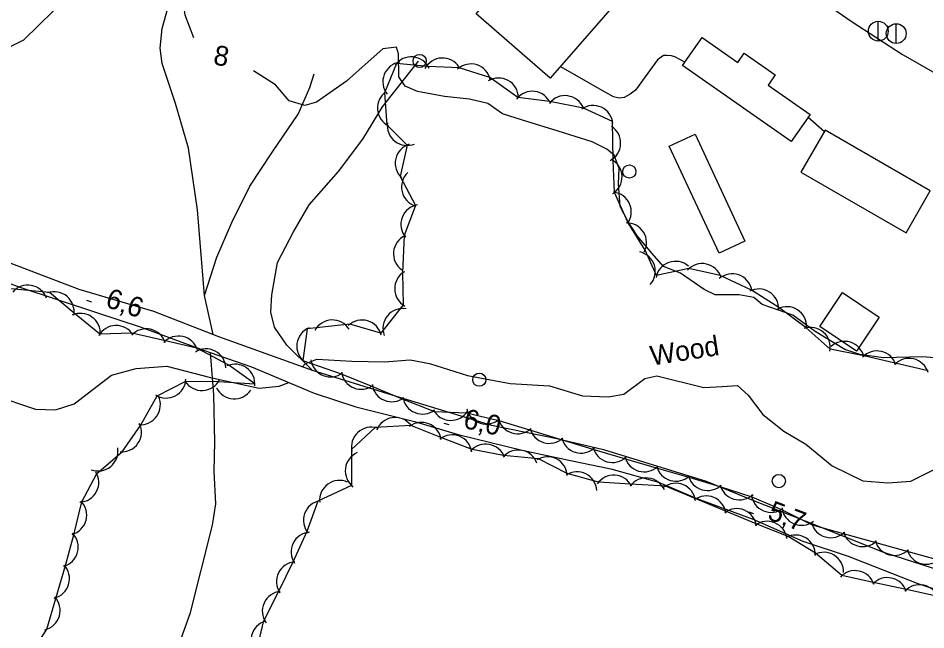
# Model space of a CAD drawing. Extents: x 646142 to 649934, y 5874075 to 5876351.
# Drawn here: x 646580.4 to 646717.7, y 5874651.3 to 5874743.9 of the extents above; entities that cross this region are included whole.
import ezdxf

# ---------------------------------------------------------------- set-up
doc = ezdxf.new("R2010")
doc.units = 0
for name, color, linetype in [('Niveau 19', 7, 'Continuous'), ('Niveau 2', 7, 'Continuous'), ('Niveau 21', 7, 'Continuous'), ('Niveau 22', 7, 'Continuous'), ('Niveau 3', 7, 'Continuous'), ('Niveau 31', 7, 'Continuous'), ('Niveau 36', 7, 'Continuous'), ('Niveau 44', 7, 'Continuous')]:
    doc.layers.add(name, color=color, linetype=linetype)

msp = doc.modelspace()

# ---------------------------------------------------------------- linework, layer by layer
at = {"layer": 'Niveau 19'}
for points in [[(646681.21, 5874737.17), (646679.7, 5874738.02), (646679.19, 5874738.17), (646678.52, 5874738.2), (646677.98, 5874738.18), (646677.09, 5874737.56), (646673.73, 5874732.96), (646672.93, 5874732.32), (646672.04, 5874731.85), (646671.29, 5874731.73), (646670.45, 5874731.95), (646669.14, 5874732.66), (646662.38, 5874736.51)], [(646699.88, 5874728.86), (646702.32, 5874726.69)]]:
    msp.add_lwpolyline(points, dxfattribs=at)
at = {"layer": 'Niveau 2'}
for points in [[(646606.93, 5874740.89), (646605.65, 5874744.31), (646605.35, 5874746.52), (646603.65, 5874747.15), (646600.75, 5874748.92), (646599.25, 5874748.62), (646596.57, 5874747.77), (646593.24, 5874747.5), (646589.33, 5874746.55), (646585.76, 5874745.03), (646581.21, 5874740.5), (646577.43, 5874738.67)], [(646721.94, 5874692.2), (646717.17, 5874692.58), (646711.27, 5874692.46), (646707.66, 5874692.94), (646705.43, 5874693.7), (646700.93, 5874696.45), (646697.57, 5874698.88), (646692.93, 5874700.51), (646691.67, 5874701.58), (646689.41, 5874701.99), (646685.78, 5874701.99), (646684.14, 5874702.8), (646680.54, 5874705.27), (646678, 5874706.25), (646676.25, 5874708.22), (646674.04, 5874710.86), (646672.63, 5874713.04), (646671.45, 5874715.35), (646671.16, 5874718.8), (646671.27, 5874721.09), (646670.52, 5874723.09), (646669.44, 5874724), (646667.19, 5874725.11), (646662.07, 5874726.76), (646656.66, 5874728.39), (646653.65, 5874729.38), (646651.42, 5874730.91), (646648.67, 5874731.57), (646644.88, 5874731.98), (646640.78, 5874732.77), (646638.89, 5874733.56), (646637.96, 5874734.95), (646637.9, 5874738.47), (646637.59, 5874739.44), (646635.56, 5874739.22), (646633.32, 5874737.23), (646630.04, 5874734.32), (646625.5, 5874731.14), (646623.72, 5874730.65), (646621.38, 5874731.34), (646619.3, 5874733.76), (646615.98, 5874735.88)], [(646483.74, 5874706.15), (646502.21, 5874704.49), (646520.99, 5874699.39), (646534.02, 5874696.13), (646543.68, 5874692.42), (646552.55, 5874691.13), (646563.43, 5874690.35), (646576.66, 5874686.81), (646583, 5874684.67)], [(646623.41, 5874691.08), (646623.79, 5874691.51), (646625.55, 5874692.24), (646630.86, 5874691.96), (646635.8, 5874691.82), (646639.65, 5874692.13), (646642.57, 5874691.6), (646648.35, 5874689.77), (646654.79, 5874688.57), (646660.74, 5874688.23), (646665.74, 5874686.68), (646669.63, 5874686.52), (646672, 5874686.95), (646675.14, 5874689.32), (646676.99, 5874689.7), (646684.11, 5874687.97), (646686.86, 5874688.08), (646689.19, 5874688.26), (646690.77, 5874686.8), (646693.01, 5874683.86), (646696.21, 5874681.36), (646699.54, 5874679.39), (646703.5, 5874676.12), (646708.14, 5874673.84), (646711.92, 5874673.5), (646715.42, 5874673.78), (646719.24, 5874675.67)], [(646583, 5874684.67), (646586.01, 5874684.55), (646588.87, 5874685.49), (646594.5, 5874689.82), (646598.24, 5874690.83), (646602.85, 5874691.19), (646609.45, 5874689.49), (646616.81, 5874687.84), (646619.84, 5874688.14), (646621.31, 5874688.72)]]:
    msp.add_lwpolyline(points, dxfattribs=at)
at = {"layer": 'Niveau 21'}
for points in [[(646649.75, 5874793.41), (646650.66, 5874792.4), (646655.42, 5874787.06), (646660.54, 5874781.72), (646663.9, 5874778.31), (646669.85, 5874772.26), (646679.8, 5874763.67), (646689.6, 5874755.42), (646697.07, 5874749.91), (646706.37, 5874743.38), (646714.15, 5874738.37), (646724.58, 5874732.4)], [(646574.98, 5874708.37), (646589.54, 5874702.82), (646600.85, 5874699.48), (646610.68, 5874695.68), (646624.84, 5874690.57), (646636.9, 5874686.82), (646651.95, 5874682.26), (646661.85, 5874680.23), (646668.92, 5874678.56), (646684.44, 5874673.8), (646691.61, 5874670.85), (646699.24, 5874667.81), (646711.25, 5874663.01), (646721.6, 5874659.72)], [(646574.44, 5874705.44), (646580.49, 5874703.21), (646592.21, 5874699.32), (646598.85, 5874697.14), (646608.54, 5874693.56), (646609.42, 5874693.26), (646615.67, 5874691.07), (646625.16, 5874687.12), (646631.44, 5874685.04), (646640.31, 5874682.8), (646646.93, 5874680.86), (646656.63, 5874678.46), (646663.92, 5874676.92), (646670.01, 5874675.65), (646677.21, 5874673.64), (646683.05, 5874671.16), (646691.64, 5874667.97), (646699.07, 5874664.68), (646705.94, 5874662.41), (646716.48, 5874658.31), (646723.35, 5874656.04)]]:
    msp.add_lwpolyline(points, dxfattribs=at)
at = {"layer": 'Niveau 22'}
for points in [[(646609.88, 5874695.98), (646608.57, 5874701.88), (646607.5, 5874714.86), (646606.15, 5874724.16), (646604.18, 5874730.94), (646602.15, 5874737.01), (646601.84, 5874739.33), (646602.18, 5874742.3), (646603.27, 5874746.26), (646605.18, 5874751.47), (646605.69, 5874755.26), (646605.88, 5874761.38)], [(646624.84, 5874690.57), (646621.01, 5874694.38), (646619.14, 5874697.06), (646618.6, 5874699.37), (646618.74, 5874701.96), (646619.62, 5874706.86), (646622.05, 5874711.52), (646624.41, 5874715.58), (646628.81, 5874720.63), (646632.51, 5874725.51), (646635.5, 5874730.45), (646640.91, 5874737.34)], [(646608.57, 5874701.88), (646610.44, 5874707.68), (646612.71, 5874712.91), (646615.42, 5874718.42), (646618.86, 5874723.63), (646622.73, 5874729.34), (646624.51, 5874733.36), (646625.16, 5874735.41)], [(646609.42, 5874693.26), (646609.95, 5874686.83), (646610.07, 5874679.66), (646609.96, 5874675.29), (646610.25, 5874670.37), (646609.7, 5874667.14), (646606.34, 5874653.68), (646603.47, 5874645.67), (646600.89, 5874639.92), (646598.04, 5874633.09), (646593.77, 5874623.55), (646589.9, 5874614.74), (646587.71, 5874611.26), (646584.25, 5874607.56), (646576.45, 5874597.85)]]:
    msp.add_lwpolyline(points, dxfattribs=at)
at = {"layer": 'Niveau 3'}
for p, q in [((646590.71, 5874701.19), (646591.46, 5874700.94)), ((646644.76, 5874682.55), (646645.54, 5874682.37)), ((646690.87, 5874669.16), (646691.62, 5874668.87))]:
    msp.add_line(p, q, dxfattribs=at)
at = {"layer": 'Niveau 31'}
for points in [[(646649.66, 5874744.52), (646661.85, 5874758.54), (646673.05, 5874748.81), (646660.87, 5874734.78), (646649.66, 5874744.52)], [(646697.32, 5874725.18), (646680.86, 5874736.68), (646683.82, 5874740.92), (646689.22, 5874737.15), (646690.19, 5874738.54), (646694.89, 5874735.25), (646693.8, 5874733.69), (646700.16, 5874729.25), (646697.32, 5874725.18)], [(646682.76, 5874726.28), (646690.29, 5874710.11), (646686.39, 5874708.29), (646678.86, 5874724.47), (646682.76, 5874726.28)], [(646718.33, 5874717.72), (646702.44, 5874726.89), (646698.77, 5874720.54), (646714.67, 5874711.37), (646718.33, 5874717.72)], [(646707.18, 5874693.47), (646701.62, 5874697.18), (646705.04, 5874702.31), (646710.6, 5874698.6), (646707.18, 5874693.47)]]:
    msp.add_lwpolyline(points, dxfattribs=at)
at = {"layer": 'Niveau 36'}
for p, q in [((646710.48, 5874740.37), (646710.48, 5874743.37)), ((646713.2, 5874740), (646713.2, 5874743))]:
    msp.add_line(p, q, dxfattribs=at)
for centre, radius in [((646710.47, 5874741.88), 1.5), ((646713.19, 5874741.51), 1.5), ((646641.1, 5874737.37), 1), ((646672.82, 5874720.63), 1), ((646650.13, 5874689.13), 1), ((646695.43, 5874673.79), 1)]:
    msp.add_circle(centre, radius, dxfattribs=at)
at = {"layer": 'Niveau 44'}
for points in [[(646718.03, 5874690.49), (646713.02, 5874691.66), (646708.29, 5874692.76), (646703.2, 5874693.76), (646699.55, 5874696.97), (646695.41, 5874700.05), (646691.31, 5874702.66), (646686.57, 5874704.92), (646681.83, 5874705.95), (646676.94, 5874704.9), (646675.2, 5874708.73), (646672.63, 5874712.85), (646670.6, 5874717.47), (646670.36, 5874722.32), (646670.28, 5874728.21), (646665.88, 5874730.25), (646660.78, 5874731.21), (646655.97, 5874731.85), (646651.71, 5874734.86), (646647.09, 5874736.35), (646642.41, 5874736.51), (646637.58, 5874736.97), (646635.8, 5874732.55), (646636.13, 5874727.7), (646639.24, 5874724.65), (646638.15, 5874719.91), (646640.46, 5874715.52), (646638.75, 5874710.98)], [(646638.75, 5874710.98), (646638.53, 5874705.3), (646638.6, 5874700.45), (646635.21, 5874696.16), (646630.55, 5874697.54), (646624.1, 5874696.85), (646623.44, 5874692.04), (646629.21, 5874690.01), (646633.98, 5874688.08), (646638.48, 5874686.26), (646643.34, 5874684.3), (646648.19, 5874684.12), (646653.1, 5874682.97), (646657.74, 5874681.55), (646662.66, 5874680.05), (646667.3, 5874678.63), (646672.24, 5874677.18), (646676.9, 5874675.81), (646681.84, 5874674.36), (646686.49, 5874672.99), (646691.35, 5874671.39), (646695.81, 5874669.48), (646700.48, 5874667.18), (646705.16, 5874665.88), (646710.11, 5874664.49), (646714.79, 5874663.19), (646719.75, 5874661.81)], [(646579.34, 5874637.38), (646580.68, 5874642.35), (646581.95, 5874647.04), (646584.73, 5874651.39), (646586.1, 5874656.04), (646587.55, 5874660.99), (646588.79, 5874665.68), (646590.02, 5874670.63), (646592.26, 5874674.93), (646596.1, 5874678.22), (646598.87, 5874682.2), (646601.42, 5874686.67), (646605.72, 5874688.92), (646610.68, 5874688.85), (646616.18, 5874688.5), (646612.23, 5874691.33), (646607.39, 5874693.93), (646602.65, 5874694.99), (646597.57, 5874696.17), (646592.72, 5874696.04), (646588.84, 5874699.21), (646585.14, 5874702.35), (646579.25, 5874702.88)], [(646678.28, 5874673.04), (646673, 5874673.32), (646668.15, 5874673.61), (646663.4, 5874674.94), (646659.08, 5874677.14), (646653.81, 5874677.68), (646649.03, 5874678.55), (646644.29, 5874680.39), (646639.79, 5874682.21), (646634.37, 5874681.89), (646630.8, 5874678.59), (646630.82, 5874673.13), (646625.7, 5874670.74), (646624.05, 5874666.18), (646621.94, 5874661.53), (646619.79, 5874657.17), (646617.46, 5874652.49), (646616.33, 5874647.77)], [(646719.48, 5874656.3), (646714.74, 5874657.36), (646709.71, 5874658.45), (646704.96, 5874659.48), (646700.96, 5874662.87), (646696.82, 5874665.4), (646691.99, 5874667.32), (646687.51, 5874669.19), (646682.76, 5874671.17), (646678.28, 5874673.04)]]:
    msp.add_lwpolyline(points, dxfattribs=at)
for centre, start, end in [((646638.54, 5874734.22), 98.7346, 218.7126), ((646639.83, 5874734.99), 24.601, 144.5789), ((646644.57, 5874734.82), 32.9625, 152.9405), ((646648.86, 5874733.92), 12.152, 132.13), ((646653.04, 5874731.78), 1.1053, 121.0832), ((646637.72, 5874730.24), 123.8021, 243.7801), ((646658.14, 5874729.78), 22.4426, 142.4205), ((646663.1, 5874729.12), 22.4426, 142.4205), ((646667.34, 5874727.63), 5.1796, 125.1575), ((646639.21, 5874727.58), 172.0628, 292.0407), ((646668.51, 5874724.94), 297.6346, 57.6126), ((646640.41, 5874721.89), 107.1064, 227.0843), ((646668.72, 5874719.81), 302.7729, 62.7508), ((646641.36, 5874718.29), 133.1452, 253.1232), ((646670.12, 5874714.52), 323.7686, 83.7465), ((646641.26, 5874712.63), 99.4211, 219.399), ((646672.42, 5874709.86), 331.9902, 91.9682), ((646640.14, 5874708.21), 114.5865, 234.5644), ((646673.75, 5874705.54), 317.6941, 77.672), ((646679.81, 5874704.05), 49.5627, 169.5407), ((646683.83, 5874703.71), 17.6861, 137.664), ((646640.33, 5874702.9), 120.8117, 240.7896), ((646688.38, 5874702.16), 10.5821, 130.56), ((646581.85, 5874700.45), 19.984, 139.962), ((646692.41, 5874699.87), 357.5355, 117.5135), ((646585.84, 5874699.44), 349.6026, 109.5805), ((646696.63, 5874697.18), 357.5355, 117.5135), ((646589.81, 5874696.17), 354.7841, 114.762), ((646638.56, 5874696.9), 80.6692, 200.6471), ((646627.9, 5874695.17), 32.0854, 152.0634), ((646632.38, 5874695.16), 13.5181, 133.4961), ((646595.2, 5874694.34), 31.5604, 151.5384), ((646599.76, 5874693.83), 17.3444, 137.3224), ((646625.52, 5874694.21), 112.237, 232.2149), ((646700.22, 5874694.04), 348.7464, 108.7243), ((646604.64, 5874692.74), 17.3444, 137.3224), ((646705.36, 5874691.94), 12.7427, 132.7206), ((646608.8, 5874690.8), 2.7049, 122.6829), ((646710.26, 5874690.49), 16.9197, 136.8977), ((646627.62, 5874692.55), 187.9962, 307.9741), ((646715.13, 5874689.36), 16.9197, 136.8977), ((646613.18, 5874688.48), 354.2805, 114.2585), ((646602.76, 5874689.36), 237.5838, 357.5617), ((646608.18, 5874690.5), 212.6044, 332.5824), ((646632.26, 5874690.68), 187.9962, 307.9741), ((646613.08, 5874689.24), 206.1603, 326.1383), ((646636.89, 5874688.8), 187.9962, 307.9741), ((646598.89, 5874685.32), 265.2307, 25.2087), ((646641.53, 5874686.93), 187.9962, 307.9741), ((646645.82, 5874685.97), 207.9913, 327.9693), ((646651.15, 5874685.41), 193.0362, 313.0141), ((646596.04, 5874681.22), 265.2307, 25.2087), ((646637.41, 5874680.41), 38.6852, 158.6632), ((646641.38, 5874679.67), 7.9981, 127.9761), ((646655.93, 5874683.95), 193.0362, 313.0141), ((646633.78, 5874678.95), 72.762, 192.7399), ((646660.72, 5874682.49), 193.0362, 313.0141), ((646646.01, 5874677.79), 7.9981, 127.9761), ((646665.5, 5874681.02), 193.0362, 313.0141), ((646592.48, 5874678.32), 249.3886, 9.3665), ((646651.1, 5874676.38), 19.7065, 139.6844), ((646656.02, 5874675.49), 19.7065, 139.6844), ((646670.27, 5874679.6), 193.603, 313.581), ((646632.85, 5874675.34), 113.4537, 233.4316), ((646660.44, 5874674.47), 3.0311, 123.0091), ((646675.07, 5874678.19), 193.603, 313.581), ((646679.87, 5874676.78), 193.6343, 313.6123), ((646589.58, 5874673.59), 272.5231, 32.501), ((646664.9, 5874672.2), 3.0311, 123.0091), ((646670.47, 5874671.7), 26.587, 146.565), ((646675.37, 5874671.26), 23.8325, 143.8104), ((646684.66, 5874675.36), 193.6343, 313.6123), ((646628.97, 5874670.9), 65.8326, 185.8105), ((646679.84, 5874670.47), 7.3795, 127.3575), ((646689.46, 5874673.95), 193.6343, 313.6123), ((646684.45, 5874668.55), 7.3795, 127.3575), ((646694.27, 5874672.06), 186.8917, 306.8696), ((646587.75, 5874668.62), 285.149, 45.1269), ((646626.53, 5874667.86), 100.1463, 220.1243), ((646689.07, 5874666.62), 7.3795, 127.3575), ((646698.87, 5874670.1), 186.8917, 306.8696), ((646693.68, 5874664.7), 7.3795, 127.3575), ((646703.29, 5874668.22), 194.4477, 314.4256), ((646586.47, 5874663.79), 285.149, 45.1269), ((646624.65, 5874663.06), 93.8009, 213.7788), ((646708.11, 5874666.88), 194.4477, 314.4256), ((646697.96, 5874662.63), 358.498, 118.476), ((646712.92, 5874665.54), 194.4477, 314.4256), ((646717.74, 5874664.2), 194.4477, 314.4256), ((646702.23, 5874660.02), 358.498, 118.476), ((646585.14, 5874659.01), 283.6005, 43.5784), ((646622.45, 5874658.57), 93.8009, 213.7788), ((646706.96, 5874657.24), 17.7848, 137.7627), ((646711.85, 5874656.18), 17.7848, 137.7627), ((646716.72, 5874655.1), 17.3918, 137.3697), ((646583.73, 5874654.21), 283.6005, 43.5784), ((646620.31, 5874654.11), 95.839, 215.817), ((646618.61, 5874649.72), 106.5227, 226.5007)]:
    msp.add_arc(centre, 3, start, end, dxfattribs=at)

# ---------------------------------------------------------------- texts
at = {"layer": 'Niveau 2'}
msp.add_text('8', height=3, rotation=349.5914, dxfattribs=at).set_placement((646609.77, 5874736.88))
at = {"layer": 'Niveau 3'}
for s, rotation, p in [('6,6  ', 341.1995, (646593.42, 5874700.23)), ('6,0  ', 347.1391, (646647.56, 5874681.87)), ('5,7  ', 339.1357, (646693.55, 5874668.09))]:
    msp.add_text(s, height=3, rotation=rotation, dxfattribs=at).set_placement(p)
at = {"layer": 'Niveau 44'}
msp.add_text('Wood', height=3, rotation=8.9405, dxfattribs=at).set_placement((646676.22, 5874691.25))

doc.saveas('drawing.dxf')
